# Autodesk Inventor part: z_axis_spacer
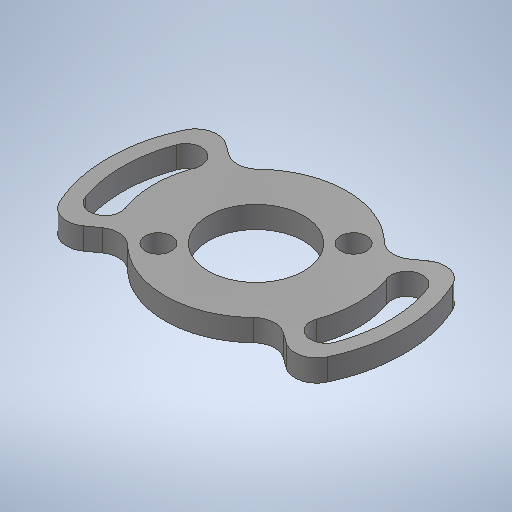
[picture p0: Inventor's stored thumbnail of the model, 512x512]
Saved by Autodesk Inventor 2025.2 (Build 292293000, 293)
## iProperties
Created: 2025-04
Part Number: z_axis_spacer
Material: 1.0037 S235JR
Document SubType Name: Modeling
Designer: BennF
Density: 7.85 g/cm^3
Appearance: Stahl
Author: BennF
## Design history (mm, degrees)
sketch "Sketch2"
  geometry: L1 (-16.2, 0)-(0, 0); L2 (0, 0)-(16.2, 0); L3 (-15.223, 5.541)-(0, 0); L4 (-15.223, -5.541)-(0, 0); C1 r 6.575 at (0, 0); C2 r 12.5 at (0, 0); C3 r 20.35 at (0, 0); A1 r 16.2 centre (0, 0) between (-15.223, 5.541) and (-15.223, -5.541); A2 r 18.35 centre (0, 0) between (-17.243, 6.276) and (-17.243, -6.276); A3 r 14.05 centre (0, 0) between (-13.203, 4.805) and (-13.203, -4.805); A4 r 2.15 centre (-15.223, 5.541) between (-13.203, 4.805) and (-17.243, 6.276); A5 r 2.15 centre (-15.223, -5.541) between (-17.243, -6.276) and (-13.203, -4.805); A6 r 16.2 centre (0, 0) between (15.223, -5.541) and (15.223, 5.541); A7 r 18.35 centre (0, 0) between (17.243, -6.276) and (17.243, 6.276); A8 r 14.05 centre (0, 0) between (13.203, -4.805) and (13.203, 4.805); A9 r 2.15 centre (15.223, -5.541) between (13.203, -4.805) and (17.243, -6.276); A10 r 2.15 centre (15.223, 5.541) between (17.243, 6.276) and (13.203, 4.805); 1 further point
  constraints: 22 point on circle, 13 centre point, 8 end point, 8 tangent, 5 coincident, 4 horizontal alignment, 2 collinear, 1 equal radius, 1 horizontal
  dimensions: "d0" = 13.15 diameter of C1; "d1" = 25 diameter of C2; "d3" = 2.15 radius of A4; "d6" = 3.7 radial gap between concentric circles of C2 A1; "d7" = 2 radial gap between concentric circles of C3 A2; "d17" = 40 deg angle of L4 L3
extrude "Extrusion1" new body sketch "Sketch2" distance "d4" = 3; taper "d5" = 0 deg
sketch "Sketch3"
  geometry: L1 (-6.718, -6.718)-(6.718, 6.718); L2 (-15.223, -5.541)-(15.223, 5.541); L3 (-9.5, 0)-(9.5, 0); A1 r 9.5 centre (0, 0) between (6.718, 6.718) and (-6.718, -6.718); A2 r 2.15 centre (-15.223, -5.541) between (-17.243, -6.276) and (-13.203, -4.805) reference; A3 r 2.15 centre (15.223, 5.541) between (17.243, 6.276) and (13.203, 4.805) reference; 3 further points
  constraints: 6 end point, 4 coincident, 4 point on circle, 3 midpoint, 1 centre point, 1 horizontal
  dimensions: "d15" = 19 diameter of A1; "d23" = 45 deg angle of L3 L1
hole "Hole1" sketch "Sketch3" at (6.718, 6.718), (-6.718, -6.718) diameter "d8" = 3.6; stored, may be unused: countersink angle "d12" = 90 deg, drill point angle "d14" = 0 deg; dims "d9" = 8, "d10" = 4, "d11" = 2, "d13" = 11.8
sketch "Sketch4"
  geometry: L1 (-10.239, 7.17)-(-16.67, 11.672); L2 (10.239, 7.17)-(16.67, 11.672); L3 (10.239, -7.17)-(16.67, -11.672); L4 (-10.239, -7.17)-(-16.67, -11.672); A1 r 12.5 centre (0, 0) between (10.239, 7.17) and (-10.239, 7.17); A2 r 12.5 centre (0, 0) between (-10.239, -7.17) and (10.239, -7.17); A3 r 20.35 centre (0, 0) between (-16.67, 11.672) and (16.67, 11.672) reference; 1 further point
  constraints: 8 end point, 8 point on circle, 4 line through centre, 2 centre point, 2 coincident, 2 vertical alignment, 1 collinear, 1 concentric
  dimensions: "d18" = 12.5 radius of A1 (= 0.5 x d1); "d19" = 70 deg angle of L4 L1
extrude "Extrusion2" cut sketch "Sketch4" stored distance "d20" = 5; taper "d21" = 0 deg
fillet "Fillet1" dims "d22" = 3
body "Solid1"
